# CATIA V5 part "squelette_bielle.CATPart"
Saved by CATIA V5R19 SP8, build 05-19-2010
Part number: squelette_bielle
Publications: "Plan.1", "Droite.1", "Droite.2"
Bounding box of the stored display mesh (mm): x 0 to 0, y -28 to 0, z -84 to 0
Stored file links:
  C:\Users\ThinkMotion\Desktop\EU_thinkMotion\iao\IAO_MMS_Groupe3\pmayet\pmayet_avant_optimisation\pmayet_avant_optimisation\squelette_bielle.CATPart
  C:\Users\ThinkMotion\Desktop\EU_thinkMotion\iao\IAO_MMS_Groupe3\pmayet\pmayet_avant_optimisation\pmayet_avant_optimisation\squelette.CATProduct
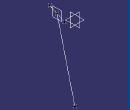
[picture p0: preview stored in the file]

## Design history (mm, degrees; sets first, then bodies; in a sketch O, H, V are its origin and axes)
Set1
  Point1 "Point_centre_bielle": linked copy from another document
  Point2 "Point2": linked copy from another document
  Point3 "Point3": linked copy from another document
  Point4 "PointB": linked copy from another document
Set2
  Plane1: type OffsetPt, RefPlane yz-plane, RefPoint Point1
  Line1: type PtPt, FirstPoint Point2, SecondPoint Point3
  Line2: type PtPt, FirstPoint Point1, SecondPoint Point4
Body1 (main body)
